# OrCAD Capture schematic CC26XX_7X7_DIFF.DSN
size A3; title: CC2640R2F-Q1; rev: 1.0.1
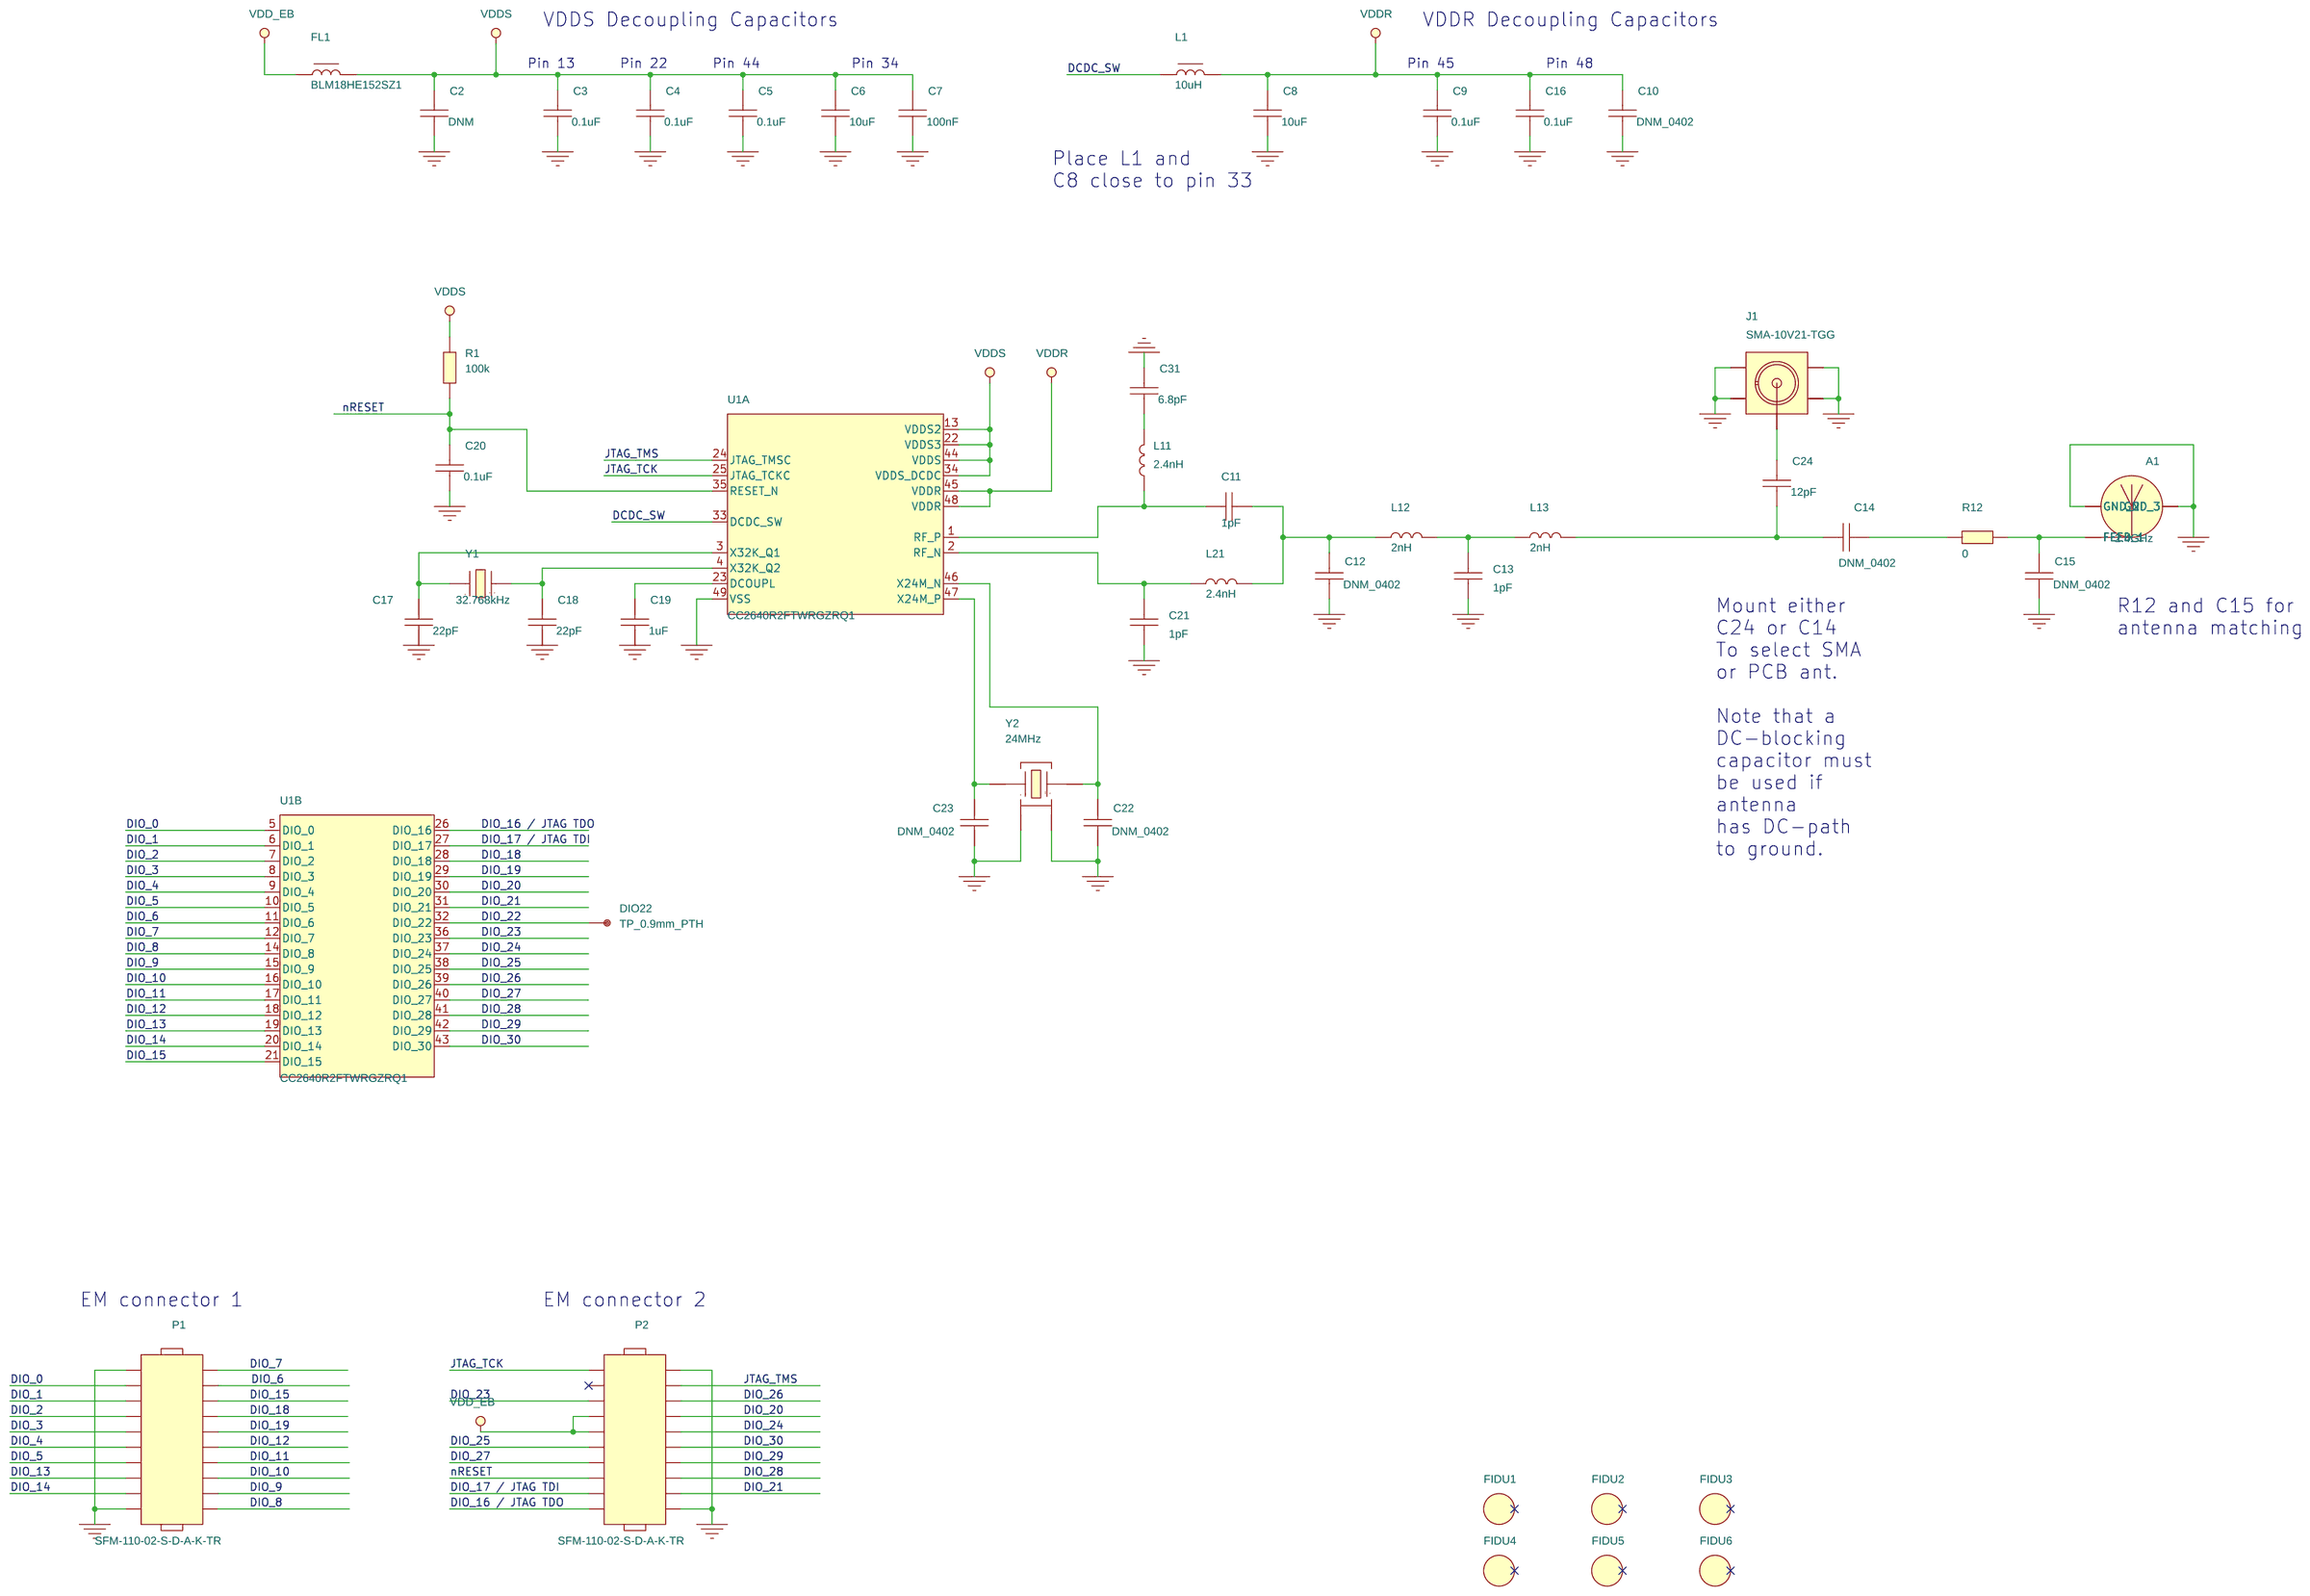
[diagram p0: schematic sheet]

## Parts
A1  2.4GHz  [ANTENNA_DN007AN]
C2  DNM  [CAPC1608X90L]
C3  0.1uF  [CAPC1005X60B2N]
C4  0.1uF  [CAPC1005X60B2N]
C5  0.1uF  [CAPC1005X60B2N]
C6  10uF  [CAPC1608X100A2N]
C7  100nF  [CAPC1608X90A2N]
C8  10uF  [CAPC1608X100A2N]
C9  0.1uF  [CAPC1005X60B2N]
C10  DNM_0402  [CAPC1005X60B2N]
C11  1pF  [CAPC1005X60B2N]
C12  DNM_0402  [CAPC1005X60B2N]
C13  1pF  [CAPC1005X60B2N]
C14  DNM_0402  [CAPC1005X60B2N]
C15  DNM_0402  [CAPC1005X60B2N]
C16  0.1uF  [CAPC1005X60B2N]
C17  22pF  [CAPC1005X60B2N]
C18  22pF  [CAPC1005X60B2N]
C19  1uF  [CAPC1005X60B2N]
C20  0.1uF  [CAPC1005X60B2N]
C21  1pF  [CAPC1005X60B2N]
C22  DNM_0402  [CAPC1005X60B2N]
C23  DNM_0402  [CAPC1005X60B2N]
C24  12pF  [CAPC1005X60B2N]
C31  6.8pF  [CAPC1005X60B2N]
DIO22  TP_0.9mm_PTH  [TP150_90H]
FIDU1  FIDU_1MM  [FID100X115]
FIDU2  FIDU_1MM  [FID100X115]
FIDU3  FIDU_1MM  [FID100X115]
FIDU4  FIDU_1MM  [FID100X115]
FIDU5  FIDU_1MM  [FID100X115]
FIDU6  FIDU_1MM  [FID100X115]
FL1  BLM18HE152SZ1  [FILC1608X100A2N]
J1  SMA-10V21-TGG  [HUSTSAN_SMA10V21TGGAN]
L1  10uH  [INDC2012X150A2N]
L11  2.4nH  [INDC1005X60B2N]
L12  2nH  [INDC1005X60B2N]
L13  2nH  [INDC1005X60B2N]
L21  2.4nH  [INDC1005X60B2N]
P1  SFM-110-02-S-D-A-K-TR  [SAMTEC_SFM11002AN]
P2  SFM-110-02-S-D-A-K-TR  [SAMTEC_SFM11002AN]
R1  100k  [RESC1005X40B2N]
R12  0  [RESC1005X40B2N]
U1  CC2640R2FTWRGZRQ1  [QFNFC50P700X700X100-49A2N]  (sections A,B)
Y1  32.768kHz  [XTAL_FC13A_A2N]
Y2  24MHz  [OSCCC250X320X60-4L]

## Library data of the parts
A1 = ANTENNA_DN007: MECHANIC, 2.4GHz INVERTED F ANTENNA, SMD; AutoDoc File: http://notefied-dynamic-precision.com/DB/Apps/Desktop/Item/Object.aspx?id=85542; Budget Currency: N/A; Budget Price: N/A; Datasheet URL 1: http://www.ti.com/lit/er/swrz002d/swrz002d.pdf; Datasheet URL 2: http://www.ti.com/lit/ds/symlink/cc2500.pdf; Definied Quality: INDUSTRIAL; Esd Level: HBM 500V; FPLIST: ANTENNA_DN007N,ANTENNA_DN007AN,; Last Time Buy: N/A; Lead Time: N/A; MPN: DN007; MPN Status: ACTIVE; MSL: N/A; MTBF: N/A; MTBF Standard: N/A; Manufacturer: TEXAS INSTRUMENTS; Max Oper Temp: +85DEGC; Min Oper Temp: -40DEGC; Mounting Type: SMD; NOTE Status: PREFERRED; Old Footprint: ANTENNA_DN007N,ANTENNA_DN007AN; Packing Size: N/A; Packing Type: N/A; Part Number: 13-00347; Part Type: MECHANIC\ANTENNA; Revision: R006; RoHS Status: LEADED; WEIGHT: N/A
C2 = CAPACITOR: CAPACITOR, DO NOT MOUNT, 0603, SMD; ALT_SYMBOLS: CAPC1608X90L,CAPC1608X90M; AutoDoc File: http://notefied-dynamic-precision.com/DB/Apps/Desktop/Item/Object.aspx?id=50475; FPLIST: CAPC1608X90N,CAPC1608X90L,CAPC1608X90M; Old Footprint: CAPC1608X90N,0603; Part Number: 02-01324; Part Type: CAPACITOR\CERAMIC\0603; Revision: R003
C3-C5 C9 C16 C20 = CAPACITOR: CAPACITOR, CERAMIC X7R, 0.1uF, 16V, -10%/+10%, -55DEGC/+125DEGC, 0402, SMD; AutoDoc File: https://notefied-dynamic-precision.com/DB/Apps/Desktop/Item/Object.aspx?id=117045; BU Name: TEXAS INSTRUMENTS NORWAY; Client Status: UNDER_REVIEW; Datasheet URL 1: http://www.murata.com/~/media/webrenewal/support/library/catalog/products/capacitor/mlcc/c03e.ashx?la=en-gb; Datasheet URL 2: http://search.murata.co.jp/Ceramy/image/img/A01X/G101/ENG/GRT155R71C104KE01-01.pdf; Dielectric Type: X7R; Last Time Buy: N/A; Max Oper Temp: +125DEGC; Max Tol: +10%; Min Oper Temp: -55DEGC; Min Tol: -10%; Mounting Type: SMD; PCB Package: 0402; Packing Size: 10000; Packing Type: TAPE_&_REEL; Part Number: 02-08025; Part Type: CAPACITOR\CERAMIC\0402\STANDARD; REACH/SVHC_COMPLIANCE: COMPLIANT; REACH/SVHC_DETAILS: SVHC List Version Jan 12, 2017; REACH/SVHC_SOURCE: REACH DECLARATION; REACH/SVHC_STATUS: UNAFFECTED; Revision: R001; RoHS Status: ROHS_COMPLIANT; Rtd Voltage: 16V; Vendor: MURATA; Vendor Part Number: GRT155R71C104KE01D; Vendor Part Status: ACTIVE
C6 C8 = CAPACITOR: CAPACITOR, CERAMIC X6S, 10uF, 10V, -20%/+20%, -55DEGC/+105DEGC, 0603, SMD; ALT_SYMBOLS: CAPC1608X100A2L,CAPC1608X100A2M; AutoDoc File: https://notefied-dynamic-precision.com/DB/Apps/Desktop/Item/Object.aspx?id=114998; BU Name: DYNAMIC PRECISION GDANSK; Client Status: UNDER_REVIEW; Datasheet URL 1: http://psearch.en.murata.com/capacitor/product/GRT188C81A106ME13%23.pdf?graph=e32930247cd2da3b6fc5ccd8f3cf2bf2; Datasheet URL 2: N/A; Definied Quality: INDUSTRIAL; Dielectric Type: X6S; Esd Level: N/A; MPN: GRM188R60J106ME47D; MPN Status: NRND; MSL: 1; MTBF: N/A; MTBF Standard: N/A; Manufacturer: MURATA; Max Oper Temp: +105DEGC; Max Tol: +20%; Min Oper Temp: -55DEGC; Min Tol: -20%; Mounting Type: SMD; NOTE Status: PREFERRED; Old Footprint: CAPC1608X90N; PCB Package: 0603; Packing Size: 4000; Packing Type: TAPE_&_REEL; Part Number: 02-07836; Part Type: CAPACITOR\CERAMIC\0603\STANDARD; Revision: R001; RoHS Status: ROHS_COMPLIANT; Rtd Voltage: 10V; Vendor: MURATA; Vendor Part Number: GRT188C81A106ME13D; Vendor Part Status: ACTIVE; WEIGHT: 0.0091g
C7 = CAPACITOR: CAPACITOR, CERAMIC X7R, 100nF, 25V, -10%/+10%, -55DEGC/+125DEGC, 0603, SMD; ALT_SYMBOLS: CAPC1608X90A2L,CAPC1608X90A2M; AutoDoc File: https://notefied-dynamic-precision.com/DB/Apps/Desktop/Item/Object.aspx?id=114997; BU Name: DYNAMIC PRECISION GDANSK; Cage Code: C0151; Client Status: UNDER_REVIEW; Datasheet URL 1: http://psearch.en.murata.com/capacitor/product/GCM188R71E104KA57%23.pdf; Datasheet URL 2: N/A; Dielectric Type: X7R; MPN: GRM188R71E104KA01D; MPN Status: ACTIVE; Manufacturer: MURATA; Max Oper Temp: +125DEGC; Max Tol: +10%; Min Oper Temp: -55DEGC; Min Tol: -10%; Mounting Type: SMD; NOTE Status: PREFERRED; Old Footprint: CAPC1608X90N,0603; PCB Package: 0603; Packing Size: 4000; Packing Type: TAPE_&_REEL; Part Number: 02-07835; Part Type: CAPACITOR\CERAMIC\0603\STANDARD; Revision: R001; RoHS Status: ROHS_COMPLIANT; Rtd Voltage: 25V; Vendor: MURATA; Vendor Part Number: GCM188R71E104KA57D; Vendor Part Status: ACTIVE; WEIGHT: 0.0063g
C10 C12 C14 C15 C22 C23 = CAPACITOR: CAPACITOR, CERAMIC, TBD, -55DEGC/+125DEGC, 0402, DNM, SMD; AutoDoc File: https://notefied-dynamic-precision.com/DB/Apps/Desktop/Item/Object.aspx?id=113344; BU Name: TEXAS INSTRUMENTS NORWAY; Budget Currency: USD; Budget Price: 0.00589; Country of Origin: MISSING INFO; Datasheet URL 1: N/A; Datasheet URL 2: N/A; Dielectric Type: MISSING-INFO; Last Time Buy: N/A; Lead Time: N/A; MPN: CAPACITOR_0402_DNM_N/A_M; MPN Status: ACTIVE; Manufacturer: Manufacturer selection; Max Oper Temp: +125DEGC; Min Oper Temp: -55DEGC; Mounting Type: SMD; NOTE Status: PREFERRED; Old Footprint: CAPC1005X60N; PCB Package: 0402; Packing Size: 10000; Packing Type: TAPE_&_REEL; Part Number: 02-07616; Part Type: CAPACITOR\CERAMIC\0402\STANDARD; Revision: R000; RoHS Status: MISSING_INFO; Vendor: MANUFACTURER SELECTION; Vendor Part Number: CAPACITOR_0402_DNM_N/A_M; Vendor Part Status: ACTIVE; Weight: N/A
C11 C13 C21 = CAPACITOR: CAPACITOR, CERAMIC C0G/NP0, 1pF, 50V, -0.25pF/+0.25pF, -55DEGC/+125DEGC, 0402, SMD; AutoDoc File: https://notefied-dynamic-precision.com/DB/Apps/Desktop/Item/Object.aspx?id=114996; BU Name: TEXAS INSTRUMENTS NORWAY; Client Status: UNDER_REVIEW; Datasheet URL 1: http://psearch.en.murata.com/capacitor/product/GRT1555C1H1R0CA02%23.pdf?graph=a4cfaea333d584c4042e010d44604a54; Datasheet URL 2: N/A; Dielectric Type: C0G/NP0; MPN: GRM1555C1H1R0CA01D; MPN Status: ACTIVE; Manufacturer: MURATA; Max Oper Temp: +125DEGC; Max Tol: +0.25pF; Min Oper Temp: -55DEGC; Min Tol: -0.25pF; Mounting Type: SMD; NOTE Status: PREFERRED; Old Footprint: CAPC1005X60N; PCB Package: 0402; Packing Size: 10000; Packing Type: TAPE_&_REEL; Part Number: 02-07834; Part Type: CAPACITOR\CERAMIC\0402\STANDARD; Revision: R001; RoHS Status: ROHS_COMPLIANT; Rtd Voltage: 50V; Vendor: MURATA; Vendor Part Number: GRT1555C1H1R0CA02D; Vendor Part Status: ACTIVE; WEIGHT: 0.0016g
C17 C18 = CAPACITOR: CAPACITOR, CERAMIC C0G/NP0, 22pF, 25V, -5%/+5%, -55DEGC/+125DEGC, 0402, SMD; AutoDoc File: https://notefied-dynamic-precision.com/DB/Apps/Desktop/Item/Object.aspx?id=114988; BU Name: TEXAS INSTRUMENTS NORWAY; Client Status: UNDER_REVIEW; Datasheet URL 1: http://psearch.murata.com/capacitor/product/GRT1555C1E220JA02%23.pdf; Datasheet URL 2: http://psearch.en.murata.com/capacitor/product/GRT1555C1E220JA02%23.html; Dielectric Type: C0G/NP0; Last Time Buy: N/A; Max Oper Temp: +125DEGC; Max Tol: +5%; Min Oper Temp: -55DEGC; Min Tol: -5%; Mounting Type: SMD; PCB Package: 0402; Packing Size: 10000; Packing Type: TAPE_&_REEL; Part Number: 02-07830; Part Type: CAPACITOR\CERAMIC\0402\STANDARD; REACH/SVHC_COMPLIANCE: COMPLIANT; REACH/SVHC_DETAILS: SVHC List Version Jan 12, 2017; REACH/SVHC_SOURCE: REACH DECLARATION; REACH/SVHC_STATUS: UNAFFECTED; Revision: R002; RoHS Status: ROHS_COMPLIANT; Rtd Voltage: 25V; Vendor: MURATA; Vendor Part Number: GRT1555C1E220JA02D; Vendor Part Status: ACTIVE; Weight: 0.0016g
C19 = CAPACITOR: CAPACITOR, CERAMIC X7S, 1uF, 10V, -10%/+10%, -55DEGC/+125DEGC, 0402, SMD; AutoDoc File: https://notefied-dynamic-precision.com/DB/Apps/Desktop/Item/Object.aspx?id=114990; BU Name: TEXAS INSTRUMENTS NORWAY; Client Status: UNDER_REVIEW; Datasheet URL 1: http://psearch.en.murata.com/capacitor/product/GRT155C71A105KE13%23.pdf?graph=e32930247cd2da3b6fc5ccd8f3cf2bf2; Datasheet URL 2: N/A; Definied Quality: INDUSTRIAL; Dielectric Type: X7S; Esd Level: N/A; MPN: GRM155R61A105KE15D; MPN Status: ACTIVE; MSL: 1; MTBF: N/A; MTBF Standard: N/A; Manufacturer: MURATA; Max Oper Temp: +125DEGC; Max Tol: +10%; Min Oper Temp: -55DEGC; Min Tol: -10%; Mounting Type: SMD; NOTE Status: PREFERRED; Old Footprint: CAPC1005X60N,0402; PCB Package: 0402; Packing Size: 10000; Packing Type: TAPE_&_REEL; Part Number: 02-07832; Part Type: CAPACITOR\CERAMIC\0402\STANDARD; Revision: R001; RoHS Status: ROHS_COMPLIANT; Rtd Voltage: 10V; Vendor: MURATA; Vendor Part Number: GRT155C71A105KE13D; Vendor Part Status: ACTIVE; WEIGHT: 0.0016g
C24 = CAPACITOR: CAPACITOR, CERAMIC C0G/NP0, 12pF, 50V, -5%/+5%, -55DEGC/+125DEGC, 0402, SMD; AutoDoc File: https://notefied-dynamic-precision.com/DB/Apps/Desktop/Item/Object.aspx?id=114995; BU Name: TEXAS INSTRUMENTS NORWAY; Client Status: UNDER_REVIEW; Datasheet URL 1: http://psearch.murata.com/capacitor/product/GRT1555C1H120JA02%23.pdf; Datasheet URL 2: http://psearch.en.murata.com/capacitor/product/GRT1555C1H120JA02%23.html; Dielectric Type: C0G/NP0; Last Time Buy: N/A; Max Oper Temp: +125DEGC; Max Tol: +5%; Min Oper Temp: -55DEGC; Min Tol: -5%; Mounting Type: SMD; PCB Package: 0402; Packing Size: 10000; Packing Type: TAPE_&_REEL; Part Number: 02-07833; Part Type: CAPACITOR\CERAMIC\0402\STANDARD; REACH/SVHC_COMPLIANCE: COMPLIANT; REACH/SVHC_DETAILS: SVHC List Version Jan 12, 2017; REACH/SVHC_SOURCE: REACH DECLARATION; REACH/SVHC_STATUS: UNAFFECTED; Revision: R002; RoHS Status: ROHS_COMPLIANT; Rtd Voltage: 50V; Vendor: MURATA; Vendor Part Number: GRT1555C1H120JA02D; Vendor Part Status: ACTIVE; Weight: 0.0016g
C31 = CAPACITOR: CAPACITOR, CERAMIC, C0G/NP0, 6.8pF, 50V, -0.5pF/+0.5pF, -55DEGC/+125DEGC, 0402, SMD; AutoDoc File: https://notefied-dynamic-precision.com/DB/Apps/Desktop/Item/Object.aspx?id=117046; BU Name: TEXAS INSTRUMENTS NORWAY; Client Status: UNDER_REVIEW; Datasheet URL 1: http://www.murata.com/~/media/webrenewal/support/library/catalog/products/capacitor/mlcc/c03e.ashx?la=en-gb; Datasheet URL 2: http://search.murata.co.jp/Ceramy/image/img/A01X/G101/ENG/GRT1555C1H6R8DA02-01.pdf; Dielectric Type: C0G/NP0; Last Time Buy: N/A; Max Oper Temp: +125DEGC; Max Tol: +0.5pF; Min Oper Temp: -55DEGC; Min Tol: -0.5pF; Mounting Type: SMD; PCB Package: 0402; Packing Size: 10000; Packing Type: TAPE_&_REEL; Part Number: 02-08026; Part Type: CAPACITOR\CERAMIC\0402\STANDARD; REACH/SVHC_COMPLIANCE: COMPLIANT; REACH/SVHC_DETAILS: SVHC List Version Jan 12, 2017; REACH/SVHC_SOURCE: REACH DECLARATION; REACH/SVHC_STATUS: UNAFFECTED; Revision: R001; RoHS Status: ROHS_COMPLIANT; Rtd Voltage: 50V; Vendor: MURATA; Vendor Part Number: GRT1555C1H6R8DA02D; Vendor Part Status: ACTIVE; Weight: 0.0016g
DIO22 = TEST_POINT: NON COMPONENT, TEST POINT 0.9mm, PTH; AutoDoc File: https://notefied-dynamic-precision.com/NotefiedWebServices/AutoDocs.aspx?itemid=84966; FPLIST: TP150_90H,; Part Number: 19-00299; Part Type: NON_COMPONENT\TEST_POINT; Revision: R001
FIDU1-FIDU6 = FIDMARK: FIDUCIAL MARK, ROUND 1MM; AutoDoc File: https://notefied-dynamic-precision.com/NotefiedWebServices/AutoDocs.aspx?itemid=74548; Part Number: 19-00111; Part Type: NON_COMPONENT\FIDUCIAL; Revision: R001
FL1 = FILTER_FERRITE: FILTER, EMI, FERRITE BEAD, 1500@100kHz, -25%/+25%, -55DEGC/+125DEGC, 0603, SMD; ALT_SYMBOLS: FILC1608X100A2L,FILC1608X100A2M; AutoDoc File: https://notefied-dynamic-precision.com/DB/Apps/Desktop/Item/Object.aspx?id=114854; BU Name: DYNAMIC PRECISION GDANSK; Client Status: UNDER_REVIEW; Datasheet URL 1: http://www.murata.com/en-eu/api/pdfdownloadapi?cate=luNoiseSupprFilteChipFerriBead&partno=BLM18HE152SZ1%23; Datasheet URL 2: N/A; Frequency: 100kHz; Impedance: 1500; Inductance: N/A; Max Oper Temp: +125DEGC; Max Tol: +25%; Min Oper Temp: -55DEGC; Min Tol: -25%; Mounting Type: SMD; PCB Package: 0603; Packing Size: 4000; Packing Type: TAPE_&_REEL; Part Number: 04-00839; Part Type: FILTER\EMI\FERRITE_BEAD\0402; Revision: R001; RoHS Status: ROHS_COMPLIANT; Rtd Current: 0.5A; Rtd Voltage: N/A; Vendor: MURATA; Vendor Part Number: BLM18HE152SZ1D; Vendor Part Status: ACTIVE; Weight: 0.006g
J1 = CONN_COAX_1+4: CONNECTOR, COAX RF, STRAIGHT, FEMALE, 1 PIN, SMD; ALT_SYMBOLS: HUSTSAN_SMA10V21TGGL,HUSTSAN_SMA10V21TGGM; AutoDoc File: http://notefied-dynamic-precision.com/DB/Apps/Desktop/Item/Object.aspx?id=84956; Budget Currency: USD; Budget Price: 1.21; Datasheet URL 1: http://www.hustsan.com.tw/uploaddir/product/SMA-10V21.pdf; Datasheet URL 2: http://www.hustsan.com.tw/uploaddir/product/SMA-10V21.pdf; FPLIST: HUSTSAN_SMA10V21TGGAN,HUSTSAN_SMA10V21TGGN; Lead Time: 5; MPN Status: ACTIVE; MSL: N/A; Manufacturer: HUS-TSAN; Mounting Type: SMD; NOTE Status: PREFERRED; No Of Pos: 1; Old Footprint: HUSTSAN_SMA10V21TGGAN,HUSTSAN_SMA10V21TGGN; Packing Size: 350; Packing Type: TAPE_&_REEL; Part Number: 06-02188; Part Type: CONNECTOR\COAX; Revision: R003; RoHS Status: N/A; WEIGHT: N/A
L1 = IND_CORE: INDUCTOR, STANDARD, 10uH, FERRITE CORE, -20%/+20%, 0.11A, -55DEGC/+125DEGC, 0805, SMD; ALT_SYMBOLS: INDC2012X150A2L,INDC2012X150A2M; AutoDoc File: https://notefied-dynamic-precision.com/DB/Apps/Desktop/Item/Object.aspx?id=115000; BU Name: DYNAMIC PRECISION GDANSK; Client Status: UNDER_REVIEW; Core Material: FERRITE; Datasheet URL 1: https://product.tdk.com/en/search/inductor/inductor/smd/info/print_pdf; Datasheet URL 2: N/A; Max Oper Temp: +125DEGC; Max Tol: +20%; Min Oper Temp: -55DEGC; Min Tol: -20%; Mounting Type: SMD; PCB Package: 0805; Packing Size: 2000; Packing Type: TAPE_&_REEL; Part Number: 03-07619; Part Type: INDUCTOR\STANDARD\CHIP\0805; Resistance: 0.39; Revision: R001; RoHS Status: ROHS_COMPLIANT; Rtd Current: 0.11A; Vendor: TDK; Vendor Part Number: MLZ2012N100LTD25; Vendor Part Status: ACTIVE; Weight: 0.014g
L11 L21 = INDUCTOR: INDUCTOR, RF, CHIP, NON-MAGNETIC CORE, 2.4nH, -0.3nH/+0.3nH, 0.85A, -55DEGC/+125DEGC, 0402, SMD; AutoDoc File: https://notefied-dynamic-precision.com/DB/Apps/Desktop/Item/Object.aspx?id=114853; BU Name: TEXAS INSTRUMENTS NORWAY; Client Status: UNDER_REVIEW; Core Material: NON-MAGNETIC; Datasheet URL 1: http://psearch.en.murata.com/inductor/product/LQG15HZ2N4S02%23.pdf; Datasheet URL 2: N/A; Frequency: 6GHz; MPN: LQG15HN2N4S02D; MPN Status: ACTIVE; Manufacturer: MURATA; Max Oper Temp: +125DEGC; Max Tol: +0.3nH; Min Oper Temp: -55DEGC; Min Tol: -0.3nH; Mounting Type: SMD; NOTE Status: PREFERRED; Old Footprint: INDC1005X60N; PCB Package: 0402; Packing Type: TAPE_&_REEL; Part Number: 03-07617; Part Type: INDUCTOR\RF\CHIP\0402; Resistance: 0.11; Revision: R001; RoHS Status: ROHS_COMPLIANT; Rtd Current: 0.85A; Vendor: MURATA; Vendor Part Number: LQG15HZ2N4S02D; Vendor Part Status: ACTIVE; WEIGHT: 0.001g
L12 L13 = INDUCTOR: INDUCTOR, RF, CHIP, NON-MAGNETIC CORE, 2nH, -0.3nH/+0.3nH, 0.9A, -55DEGC/+125DEGC, 0402, SMD; AutoDoc File: https://notefied-dynamic-precision.com/DB/Apps/Desktop/Item/Object.aspx?id=114852; BU Name: TEXAS INSTRUMENTS NORWAY; Client Status: UNDER_REVIEW; Core Material: NON-MAGNETIC; Datasheet URL 1: http://psearch.en.murata.com/inductor/product/LQG15HZ2N0S02%23.pdf; Datasheet URL 2: N/A; Frequency: 6GHz; MPN: LQG15HS2N0S02D; MPN Status: ACTIVE; Manufacturer: MURATA; Max Oper Temp: +125DEGC; Max Tol: +0.3nH; Min Oper Temp: -55DEGC; Min Tol: -0.3nH; Mounting Type: SMD; NOTE Status: PREFERRED; Old Footprint: INDC1005X60N; PCB Package: 0402; Packing Size: 10000; Packing Type: TAPE_&_REEL; Part Number: 03-07616; Part Type: INDUCTOR\RF\CHIP\0402; Resistance: 0.09; Revision: R001; RoHS Status: ROHS_COMPLIANT; Rtd Current: 0.9A; Vendor: MURATA; Vendor Part Number: LQG15HZ2N0S02D; Vendor Part Status: ACTIVE; WEIGHT: 0.001g
P1 P2 = CONN_HEADER_2X10_P_S: CONNECTOR, HEADER, FEMALE, STRAIGHT, 2 ROWS, 20 PINS, PITCH 1.27mm, SMD; Alt IPC Footprints: SAMTEC_SFM11002AL,SAMTEC_SFM11002AM; AutoDoc File: https://notefied-dynamic-precision.com/NotefiedWebServices/AutoDocs.aspx?itemid=85603; Datasheet URL 1: http://www.samtec.com/ProductInformation/TechnicalSpecifications/CatalogPages.aspx?series=SFM; Datasheet URL 2: http://www.samtec.com/documents/webfiles/cpdf/SFM-1XX-XX-XX-S-XX-MKT1.pdf; MPN: SFM-110-02-SM-D-A-K-TR; MPN Status: ACTIVE; Manufacturer: SAMTEC; Max Oper Temp: +125DEGC; Min Oper Temp: -55DEGC; Mounting Type: SMD; NOTE Status: PREFERRED; No Of Pos: 20; No Of Rows: 2; Packing Size: 125; Packing Type: TAPE_&_REEL; Part Number: 06-02251; Part Type: CONNECTOR\HEADER; Pitch: 1.27mm; Revision: R001; RoHS Status: ROHS_COMPLIANT
R1 = RESISTOR: RESISTOR, THICK FILM, 100k, -1%/+1%, 0.063W, 50V, -55DEGC/+155DEGC, 0402, SMD; ALT_SYMBOLS: RESC1005X40B2L,RESC1005X40B2M; AutoDoc File: https://notefied-dynamic-precision.com/DB/Apps/Desktop/Item/Object.aspx?id=115161; BU Name: TEXAS INSTRUMENTS NORWAY; Client Status: UNDER_REVIEW; Datasheet URL 1: http://www.ttelectronicsresistors.com/datasheets/WCR.pdf; Definied Quality: INDUSTRIAL; Esd Level: N/A; LifeCycle Status: ACTIVE; MPN: RESISTOR_0402_100k_+/-1%_50V_0.063W_M_+/-100PPM; MPN Status: ACTIVE; MSL: N/A; MTBF: N/A; MTBF Standard: N/A; Manufacturer: MANUFACTURER SELECTION; Max Oper Temp: +155DEGC; Max TC: +100PPM/DEGC; Max Tol: +1%; Min Oper Temp: -55DEGC; Min TC: -100PPM/DEGC; Min Tol: -1%; Mounting Type: SMD; NOTE Status: PREFERRED; Old Footprint: RESC1005X40N; PCB Package: 0402; Packing Size: 10000; Packing Type: TAPE_&_REEL; Part Number: 01-22536; Part Type: RESISTOR\0402\PRECISION; Resistor Type: THICK FILM; Revision: R001; RoHS Status: ROHS_COMPLIANT; Rtd Current: N/A; Rtd Power: 0.063W; Rtd Voltage: 50V; Vendor: TT ELECTRONICS; Vendor Part Number: WCR0402-100KFA; Vendor Part Status: ACTIVE
R12 = RESISTOR: RESISTOR, THICK FILM, 0, +5%, 0.0625W, 50V, -55DEGC/+155DEGC, 0402, SMD; ALT_SYMBOLS: RESC1005X40B2L,RESC1005X40B2M; AutoDoc File: https://notefied-dynamic-precision.com/DB/Apps/Desktop/Item/Object.aspx?id=115162; BU Name: TEXAS INSTRUMENTS NORWAY; Client Status: UNDER_REVIEW; Datasheet URL 1: http://www.yageo.com/documents/recent/PYu-AC_51_RoHS_L%205.pdf; Datasheet URL 2: N/A; Definied Quality: INDUSTRIAL; Esd Level: N/A; LifeCycle Status: ACTIVE; MPN: RK73Z1ETTP; MPN Status: ACTIVE; MSL: 1; MTBF: N/A; MTBF Standard: N/A; Manufacturer: KOA SPEER; Max Oper Temp: +155DEGC; Max Tol: +5%; Min Oper Temp: -55DEGC; Mounting Type: SMD; NOTE Status: PREFERRED; Old Footprint: RESC1005X40N,0402; PCB Package: 0402; Packing Size: 10000; Packing Type: TAPE_&_REEL; Part Number: 01-22537; Part Type: RESISTOR\0402\JUMPER; Resistor Type: THICK FILM; Revision: R001; Rtd Current: N/A; Rtd Power: 0.0625W; Rtd Voltage: 50V; Vendor: YAGEO; Vendor Part Number: AC0402JR-070RL; Vendor Part Status: ACTIVE
U1 = IC_RF_CC26XX_QFN48_V2: IC, MICROCONTROLLER, TEXAS INSTRUMENTS CC2640 AUTOMOTIVE, QFN48 WETTABLE FLANKS, SMD; ALT_SYMBOLS: QFNFC50P700X700X100-49A2L,QFNFC50P700X700X100-49A2M; AutoDoc File: https://notefied-dynamic-precision.com/DB/Apps/Desktop/Item/Object.aspx?id=115208; BU Name: TEXAS INSTRUMENTS NORWAY; Client Status: UNDER_REVIEW; Datasheet URL 1: http://www.ti.com/; Datasheet URL 2: http://www.ti.com/lit/ml/mpqf123e/mpqf123e.pdf; MPN: CC26xx_7x7_QFN48; MPN Status: ACTIVE; Manufacturer: TEXAS INSTRUMENTS; Max Oper Temp: N/A; Min Oper Temp: N/A; Mounting Type: SMD; NOTE Status: PREFERRED; Old Footprint: QFNFC50P700X700X80-49CN; PCB Package: QFN48-EP; Packing Size: N/A; Packing Type: N/A; Part Number: 18-33415; Part Type: IC\MICROCONTROLLER\TEXAS_INSTRUMENTS; Revision: R001; RoHS Status: MISSING_INFO; Rtd Voltage: N/A; Vendor: TEXAS INSTRUMENTS; Vendor Part Status: ACTIVE; Color: Default; Design_Date : 2013-02-14; Designed_By : Artur Bielinski; Location X-Coordinate: 0; Location Y-Coordinate: 0; Power Pins Visible: False; Primitive: DEFAULT; SPLIT_INST: TRUE; SWAP_INFO: (S1+S2)
Y1 = XTAL: CRYSTAL, RESONATOR, 32.768kHz, -40DEGC/+125DEGC, SMD; ALT_SYMBOLS: XTAL_FC13A_A2L,XTAL_FC13A_A2M; AutoDoc File: https://notefied-dynamic-precision.com/DB/Apps/Desktop/Item/Object.aspx?id=117355; BU Name: DYNAMIC PRECISION GDANSK; Capacitance: 12.5pF; Client Status: UNDER_REVIEW; Datasheet URL 1: https://support.epson.biz/td/api/doc_check.php?mode=dl&lang=en&Parts=FC-13A; Datasheet URL 2: http://www5.epsondevice.com/en/products/khz_range/fc13a.html; Max Oper Temp: +125DEGC; Max Tol: +20PPM; Min Oper Temp: -40DEGC; Min Tol: -20PPM; Mounting Type: SMD; Packing Size: 250; Packing Type: TAPE_&_REEL; Part Number: 12-01261; Part Type: CRYSTAL\RESONATOR; REACH/SVHC_COMPLIANCE: COMPLIANT; REACH/SVHC_DETAILS: SVHC List Version Jan 12, 2017; REACH/SVHC_SOURCE: REACH DECLARATION; REACH/SVHC_STATUS: UNAFFECTED; Revision: R001; RoHS Status: ROHS_COMPLIANT; Rtd Voltage: N/A; Vendor: EPSON; Vendor Part Number: FC-13A 32.7680KA-A3; Vendor Part Status: ACTIVE
Y2 = XTAL_4PIN_S: CRYSTAL, CRYSTAL OSCILLATOR, 24MHz, -15PPM/DEGC/+15PPM/DEGC, -40DEGC/+85DEGC, SMD; ALT_SYMBOLS: OSCCC250X320X60-4L,OSCCC250X320X60-4M; AutoDoc File: http://notefied-dynamic-precision.com/DB/Apps/Desktop/Item/Object.aspx?id=96738; Budget Currency: EUR; Budget Price: 0.256; Capacitance: 9pF; Datasheet URL 1: http://www.eea.epson.com/portal/pls/portal/docs/1/1721495.PDF; Datasheet URL 2: http://www.epsondevice.com/docs/qd/en/DownloadServlet?id=ID000658; FPLIST: OSCCC250X320X60-4N,OSCCC250X320X60-4L,OSCCC250X320X60-4M; Lead Time: 12; MPN: TSX-3225 24.0000MF15X-AC3; MPN Status: ACTIVE; Manufacturer: EPSON; Max Oper Temp: +85DEGC; Max TC: +15PPM/DEGC; Max Tol: +10PPM; Min Oper Temp: -40DEGC; Min TC: -15PPM/DEGC; Min Tol: -10PPM; Mounting Type: SMD; NOTE Status: PREFERRED; Old Footprint: OSCCC250X320X60-4N; Packing Size: 250; Packing Type: TAPE_&_REEL; Part Number: 12-00757; Part Type: CRYSTAL\OSCILLATOR; Revision: R001; RoHS Status: ROHS_COMPLIANT

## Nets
GND: A1.2(GND) A1.3(GND) C2.2 C3.2 C4.2 C5.2 C6.2 C7.2 C8.2 C9.2 C10.2 C12.2 C13.1 C15.2 C16.2 C17.2 C18.2 C19.2 C20.2 C21.1 C22.2 C23.2 C31.1 J1.2 J1.3 J1.4 J1.5 P1.1 P1.19 P2.2 P2.20 U1.49(VSS) Y2.2 Y2.4
VDD_EB: FL1.1 P2.7 P2.9
VDDR: C8.1 C9.1 C10.1 C16.1 L1.2 U1.45(VDDR) U1.48(VDDR)
VDDS: C2.1 C3.1 C4.1 C5.1 C6.1 C7.1 FL1.2 R1.2 U1.13(VDDS2) U1.22(VDDS3) U1.34(VDDS_DCDC) U1.44(VDDS)
DCDC_SW: L1.1 U1.33(DCDC_SW)
DIO_0: P1.3 U1.5(DIO_0)
DIO_1: P1.5 U1.6(DIO_1)
DIO_2: P1.7 U1.7(DIO_2)
DIO_3: P1.9 U1.8(DIO_3)
DIO_4: P1.11 U1.9(DIO_4)
DIO_5: P1.13 U1.10(DIO_5)
DIO_6: P1.4 U1.11(DIO_6)
DIO_7: P1.2 U1.12(DIO_7)
DIO_8: P1.20 U1.14(DIO_8)
DIO_9: P1.18 U1.15(DIO_9)
DIO_10: P1.16 U1.16(DIO_10)
DIO_11: P1.14 U1.17(DIO_11)
DIO_12: P1.12 U1.18(DIO_12)
DIO_13: P1.15 U1.19(DIO_13)
DIO_14: P1.17 U1.20(DIO_14)
DIO_15: P1.6 U1.21(DIO_15)
DIO_16 / JTAG TDO: P2.19 U1.26(DIO_16)
DIO_17 / JTAG TDI: P2.17 U1.27(DIO_17)
DIO_18: P1.8 U1.28(DIO_18)
DIO_19: P1.10 U1.29(DIO_19)
DIO_20: P2.8 U1.30(DIO_20)
DIO_21: P2.18 U1.31(DIO_21)
DIO_22: DIO22.1 U1.32(DIO_22)
DIO_23: P2.5 U1.36(DIO_23)
DIO_24: P2.10 U1.37(DIO_24)
DIO_25: P2.11 U1.38(DIO_25)
DIO_26: P2.6 U1.39(DIO_26)
DIO_27: P2.13 U1.40(DIO_27)
DIO_28: P2.16 U1.41(DIO_28)
DIO_29: P2.14 U1.42(DIO_29)
DIO_30: P2.12 U1.43(DIO_30)
JTAG_TCK: P2.1 U1.25(JTAG_TCKC)
JTAG_TMS: P2.4 U1.24(JTAG_TMSC)
nRESET: C20.1 P2.15 R1.1 U1.35(RESET_N)
N310466: C23.1 U1.47(X24M_P) Y2.1
N310868: C22.1 U1.46(X24M_N) Y2.3
N314427: C21.2 L21.1 U1.2(RF_N)
N314470: C11.1 L11.1 U1.1(RF_P)
N314514: C31.2 L11.2
N314764: C11.2 C12.1 L12.1 L21.2
N315193: C13.2 L12.2 L13.1
N316022: A1.1(FEED) C15.1 R12.1
N316040: C24.1 J1.1
N316649: C19.1 U1.23(DCOUPL)
N316919: C17.1 U1.3(X32K_Q1) Y1.1
N316932: C18.1 U1.4(X32K_Q2) Y1.2
N334495: C14.1 C24.2 L13.2
N356130: C14.2 R12.2

Not connected (* = marked no-connect by the designer): FIDU1 1*; FIDU2 1*; FIDU3 1*; FIDU4 1*; FIDU5 1*; FIDU6 1*; P2 3*

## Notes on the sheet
- VDDS Decoupling Capacitors
- VDDR Decoupling Capacitors
- Pin 13
- Pin 22
- Pin 44
- Pin 34
- Pin 45
- Pin 48
- Place L1 and
  C8 close to pin 33
- Mount either
  C24 or C14
  To select SMA
  or PCB ant.
  Note that a
  DC-blocking
  capacitor must
  be used if
  antenna
  has DC-path
  to ground.
- R12 and C15 for
  antenna matching
- EM connector 1
- EM connector 2
